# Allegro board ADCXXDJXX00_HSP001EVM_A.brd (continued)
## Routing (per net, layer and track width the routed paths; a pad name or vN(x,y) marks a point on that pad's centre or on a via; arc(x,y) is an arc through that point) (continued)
V3P3V:
  vias: v1(97.41,9.27) v1(97.41,7.24) v1(97.79,15.37) v1(98.3,7.75) v1(99.19,8.38) v1(99.44,15.75) v1(99.44,12.95) v1(99.49,11.33) v1(99.49,10.21) v1(100.69,13.03) v1(100.71,9.02) v1(100.97,10.54) v1(102.11,14.22) v1(102.11,11.94) v1(103.73,13) v1(104.27,11.81)
V3P3V_LMX: length 0.7
  BOTTOM w0.305: U22.20 81.5,7.71 v1(81.53,7.75)
  vias: v1(80.39,15.75) v1(80.39,14.86) v1(80.52,9.4) v1(80.52,7.37) v1(81.41,15.75) v1(81.41,14.99) v1(81.92,9.14) v1(82.17,8.38) v1(82.42,13.97) v1(82.42,12.32) v1(82.6,11.33) v1(82.6,10.21) v1(82.8,14.86) v1(83.31,15.87) v1(83.69,13.59) v1(83.82,12.45) v1(83.82,10.29) v1(83.82,9.02) v1(83.95,11.43) v1(84.96,12.32) v1(84.96,10.92) v1(85.47,9.52) v1(86.11,11.94) v1(86.11,10.79) v1(86.87,12.32) v1(87.25,10.79) v1(87.5,9.52)
V11_OUT:
  vias: v1(67.82,5.46) v1(69.09,7.37) v1(69.16,6.4) v1(69.34,5.33) v1(69.98,6.1) v1(70.48,5.33) v1(70.61,6.96) v1(71.79,6.25) v1(71.88,7.49) v1(72.01,5.23) v1(72.39,6.86) v1(72.77,6.1) v1(73.53,6.98) v1(73.53,5.23)
V19_SNS: length 12.2
  BOTTOM w0.254: FB16.1 42.29,19.18 42.55,18.92 45.47,18.92 45.47,18.93
  BOTTOM w0.305: U16.2 47.22,20.72 R149.1 46.57,20.28 U16.1 46.37,19.3 45.85,19.3 45.47,18.93 U16.20 U16.19
VBUS:
  vias: v1(32.95,14)
VBUSS: length 1.9
  BOTTOM w0.305: C173.1 31.34,16.29 31.05,16.58 v1(31.05,17.5)
VCCIN: length 2.3
  TOP w0.381: C104.2 65.88,114.68 v1(66.02,114.53)
  BOTTOM w0.305: v1(66.02,114.53) 65.92,114.64 U3.10
VDDD33: length 26.2
  TOP w0.127: U2.2 v1(25.96,111.2)
  TOP w0.254: U11.8 v1(76.2,35.48) ; U11.7 v1(76.22,36.13) ; U11.2 77.61,39.66 v1(77.62,39.66) 77.62,40.03 U11.1 U11.16
  TOP w0.305: U8.56 v1(59.31,44.61) ; v1(87.62,50.67) 87.62,49.79 U12.16 ; U8.20 v1(56.8,33.62) ; v1(62.31,33.48) U8.31 ; U8.42 v1(64.76,39.87)
  TOP w0.356: U10.2 48.66,29.33 v1(48.67,29.34) 48.67,29.57 U10.1 ; U10.8 v1(49.77,25.03) ; U10.16 v1(54.31,30.05)
  TOP w0.508: v1(74.36,46.5) v1(74.36,45.36)
  BOTTOM w0.127: C41.1 25.97,111.22 v1(25.96,111.2)
  BOTTOM w0.305: C187.1 63.31,39.87 v1(64.76,39.87) ; C189.1 59.31,44.61 v1(59.31,44.61) ; C188.1 v1(62.31,33.48) ; v1(56.8,33.62) C186.1
  BOTTOM w0.508: v1(77.02,50.71) 76.95,50.64 C180.1 ; FB12.1 51.82,43.81 v1(52.2,44.2)
  vias: v1(26.47,112.36) v1(29.26,113.25) v1(32.94,112.49) v1(32.94,111.34) v1(32.94,110.2) v1(32.94,109.06) v1(42.14,102.28) v1(42.13,99.86) v1(42.65,102.79) v1(42.65,101.77) v1(42.76,99.09) v1(43.53,99.86) v1(43.53,98.33) v1(50.55,48.13) v1(51.03,36.36) v1(51.31,47.37) v1(51.38,37.59) v1(66.88,31.3) v1(68.96,41.27) v1(68.96,38.99) v1(78.82,43.12) v1(92.08,13.34) v1(93.34,19.3) v1(93.34,16.13) v1(93.34,14.6) v1(93.34,12.06) v1(94.61,13.34) v1(96.01,16) v1(96.52,18.92) v1(96.77,18.16) v1(96.77,16.76) v1(97.16,21.59) v1(97.16,20.83) v1(97.28,19.43) v1(97.41,17.4) v1(97.82,20.19) v1(97.79,18.41) v1(98.42,19.43) v1(98.55,21.59) v1(98.55,20.83) v1(107.98,43.69) v1(110.24,39.75)
VDDL19: length 6.5
  TOP w0.305: v1(85.86,49.14) 87.57,49.14 U12.15 ; U11.15 v1(81.75,39.38)
  BOTTOM w0.508: v1(81.75,39.38) 81.78,39.41 C193.1 ; C195.1 v1(85.86,49.14)
  vias: v1(45.21,22.35) v1(45.21,20.7) v1(45.82,21.46) v1(45.97,23.24) v1(46.35,22.35) v1(46.74,22.99) v1(47.35,22.23) v1(47.62,22.99) v1(51.18,28.19) v1(51.18,27.3) v1(51.18,26.42) v1(51.69,26.92) v1(51.69,26.16) v1(51.82,28.7) v1(51.82,27.81) v1(52.32,25.78) v1(52.45,27.05) v1(52.58,28.83) v1(52.58,27.81) v1(52.83,26.29) v1(53.21,28.96) v1(54.31,28.93) v1(72.97,47.82) v1(73.05,47.04) v1(73.66,48.17) v1(73.77,47.38)
VINA: length 14.5
  TOP w0.279: J2.1 BALUN1.1
VINB: length 14.5
  TOP w0.279: J5.1 BALUN2.1
1P4V: length 2.3
  TOP w0.279: U17.6 v1(52.58,6.6) ; v1(52.58,9.91) v1(52.58,11.3)
  vias: v1(51.49,12.73) v1(51.49,11.33) v1(51.49,9.94) v1(52.58,12.7)
1P8V_USB: length 52.8
  TOP w0.305: v1(64.67,37.36) U8.37 ; U8.49 62.81,45.28 v1(63.12,45.59) ; U8.64 v1(55.3,44.51) ; v1(53.8,37.36) U8.12
  L10_SIG-2 w0.508: v1(44.07,33.4) 53.98,33.4 54.86,34.29 54.86,37.46
  BOTTOM w0.254: v1(55.3,44.51) 55.3,43.57 C181.1
  BOTTOM w0.279: v1(53.8,37.36) 54.05,37.11 C182.1 54.61,36.98 54.61,34.67 ; 65.03,37 v1(64.67,37.36) C183.1
  BOTTOM w0.305: v1(63.12,45.59) 62.81,45.28 C179.1
  BOTTOM w0.508: 65.03,37 65.41,36.62 65.41,34.6 63.32,32.51 56.77,32.51 54.61,34.67 53.34,33.4 v1(44.07,33.4)
  vias: v1(62.74,46.1) v1(63.5,45.09)
2P2V: length 0.9
  TOP w0.279: U14.6 v1(38.27,7.16)
  vias: v1(37.02,13.48) v1(37.02,12.08) v1(37.02,10.68) v1(38.27,13.34) v1(38.27,11.94) v1(38.27,10.54)
3P3USB: length 16.9
  TOP w0.305: v1(52.65,37.59) 52.65,38.02 53.51,38.88 53.94,38.88 53.95,38.87 U8.9
  BOTTOM w0.254: v1(44.07,37.21) 46.07,37.21 47.11,38.25 50.47,38.25 51.71,39.5 53.72,39.5 54.36,38.86 53.95,38.86 53.91,38.9 53.31,38.9 C171.1
  BOTTOM w0.279: v1(52.65,37.59) 53.15,38.09 53.15,38.75 C171.1
  BOTTOM w0.508: C170.1 54.36,38.86
3P3V_RX: length 19.5
  BOTTOM w0.279: v1(121.28,32.64) 123.95,32.64 125.98,34.67 137.58,34.67 139.06,36.15 v1(139.06,36.45)
3P3VAUX: length 29.7
  TOP w0.279: v1(122.73,36.45) 121.78,36.45 121.61,36.61 U5.8
  L10_SIG-2 w0.165: v1(122.73,36.45) 123.83,37.54 123.83,39.37 123.19,40 123.19,46.99
  BOTTOM w0.102: J25.D32 138.43,48.39 128.52,48.39
  BOTTOM w0.279: 123.19,46.99 124.59,48.39 128.52,48.39
12P0V_RX:
  vias: v1(140.33,45.21) v1(140.33,42.67)
ADBUS0: length 14.1
  TOP w0.279: U8.16 53.82,35.36 53.66,35.2 52.73,35.2 48.06,30.53 46.91,30.53 46.33,29.95 46.33,28.73 46.78,28.28 U10.3
ADBUS1: length 11.1
  TOP w0.279: U8.17 55.3,33.53 53.98,32.21 52.3,32.21 49.72,29.63 49.72,27.91 49.44,27.63 U10.4
ADBUS2: length 12.2
  TOP w0.279: U8.18 55.8,33.01 54.46,31.67 52.5,31.67 50.14,29.31 50.14,27.54 49.59,26.98 U10.5
ADBUS3: length 13.3
  TOP w0.279: U8.19 56.3,32.75 54.74,31.19 52.65,31.19 50.6,29.13 50.6,27.1 49.82,26.33 U10.6
ADC_CLK: length 86.9
  L04_SIG-1 w0.14: v1(43.88,45.25) 43.88,38.11 45.99,36 49.18,36 50.31,34.87 53.31,34.87 58.42,29.76 v1(58.42,29.59)
  L10_SIG-2 w0.102: v1(36.12,73.68) 35.72,74.08 33.52,74.08 33.33,74.27 33.33,77.36 33.33,77.36
  L10_SIG-2 w0.165: v1(43.88,45.25) 47.62,48.99 47.62,78.29 44.68,81.23 43.27,81.23 41.49,83 35.12,83 33.47,81.36 33.47,77.66 33.33,77.51 33.33,77.36
ADC_SCSB: length 72.3
  L04_SIG-1 w0.102: 32.62,69.16 32.52,69.26 32.52,73.07 32.74,73.28 35.51,73.28 35.73,73.5 35.73,74.08 v1(36.12,74.48)
  L04_SIG-1 w0.14: v1(58.42,26.16) 57.09,27.49 57.09,28.43 54.86,30.66 39.84,30.66 35.21,35.29 35.21,47.25 36.07,48.11 36.07,51.49 31.93,55.64 31.93,61.05 32.7,61.82 32.7,69.09 32.62,69.16
ADC_SDI: length 61.6
  L04_SIG-1 w0.089: 34.04,69.22 34.12,69.29
  L04_SIG-1 w0.102: 34.12,69.29 34.12,71.49 34.31,71.68 36.3,71.68 36.52,71.9 36.52,72.48 v1(36.12,72.88)
  L04_SIG-1 w0.14: v1(58.42,28.45) 53.6,33.27 45.55,33.27 39.9,38.92 39.9,47.08 38.14,48.84 38.14,52.74 35.64,55.25 35.64,61.14 33.99,62.78 33.99,69.16 34.04,69.22
ADC_SDO: length 67
  L04_SIG-1 w0.102: v1(36.12,72.08) 35.74,72.47 33.51,72.47 33.33,72.29 33.33,69.22
  L04_SIG-1 w0.14: 33.33,69.22 33.33,56.17 36.98,52.52 36.98,47.67 35.96,46.65 35.96,37.05 41.9,31.11 54.91,31.11 54.91,31.11 55.11,31.11 57.61,28.62 57.61,28.12 v1(58.42,27.3)
BDBUS0: length 2.9
  TOP w0.279: U8.26 59.81,31.63 R112.1
BDBUS1: length 6.4
  TOP w0.279: v1(60.31,33.55) U8.27 ; 64.18,30.35 v1(63.13,30.35)
  L10_SIG-2 w0.165: v1(60.31,33.55) 60.31,33.17 v1(63.13,30.35)
BDBUS2: length 3
  TOP w0.279: R113.1 60.81,31.78 U8.28
BDBUS3: length 5.2
  TOP w0.279: U7.1 62.93,31.3 61.31,32.93 U8.29
BYPASS: length 11.1
  BOTTOM w0.508: R159.1 FB18.1 71.81,14.25 72.57,13.49 74.78,13.49 FB19.1 74.8,11.46 73.53,10.19 73.53,9.02
CALTRG: length 30.3
  L04_SIG-1 w0.102: 34.92,78.04 34.92,77.4 35.05,77.28 35.48,77.28 35.71,77.05 35.71,76.67 35.92,76.47 36.4,76.47 36.52,76.34 36.52,75.05 36.37,74.89 35.99,74.89 35.57,74.48 v1(35.33,74.48)
  L04_SIG-1 w0.14: J9.2 36.06,96.22 34.57,94.74 34.57,86.89 33.82,86.14 33.82,80.41 34.92,79.31 34.92,78.04
  BOTTOM w0.279: R23.1 36.06,98.58 J9.2
CDBUS0: length 4.8
  TOP w0.279: U8.38 66.78,37.87 R118.1
CDBUS1: length 4.5
  TOP w0.279: U8.39 67.43,38.37 R119.1
CDBUS2: length 6.9
  TOP w0.279: U8.40 67.82,38.87 R115.2 68.58,39.62 69.34,39.62 R120.1
CDBUS3: length 7.7
  TOP w0.254: R114.2 67.94,40.51 68.33,40.13 R121.1
  TOP w0.279: U8.41 66.8,39.37 67.94,40.51
CE: length 5.3
  BOTTOM w0.279: U3.1 66.97,119.14 R46.1 67.79,119.96 68.81,119.96 JP5.2
CLK+: length 3.3
  TOP w0.279: C49.1 21.72,73.79 R43.2 20.12,74.37 arc(19.92,74.5) 19.69,74.55 T2.1
CLK-: length 3.3
  TOP w0.279: 18.86,72.01 19.69,72.01 arc(19.92,72.06) 20.12,72.19 R43.1 21.72,72.77 C52.1
CLK-IN: length 5.7
  BOTTOM w0.279: R69.1 T1.6 R67.1 R72.1 R70.2
CLK_+: length 8
  TOP w0.279: U1.F1 30.47,73.73 23.22,73.73 ; 23.22,73.73 23.04,73.73 C49.2 ; 23.22,73.73 23.22,73.73 v2(23.22,73.66)
  BOTTOM w0.279: C48.2 v2(23.22,73.66)
CLK_-: length 8
  TOP w0.279: U1.G1 30.47,72.83 23.22,72.83 ; v2(23.22,72.9) 23.22,72.83 ; 23.22,72.83 23.04,72.83 C52.2
  BOTTOM w0.279: C51.2 v2(23.22,72.9)
CLKIN0: length 27.9
  BOTTOM w0.279: R186.1 87.81,101.54 R187.1 86.26,101.54 arc(86.1,101.58) 85.96,101.67 85.73,101.89 arc(85.14,102.29) 84.43,102.43 J38.1
CLKIN0_N: length 3.7
  BOTTOM w0.254: U4.38 91.84,101.31 arc(91.09,101.46) 90.45,101.89 arc(90.26,102.01) 90.05,102.05 C24.2
CLKIN0_P: length 3.6
  BOTTOM w0.254: C20.2 90.28,101.29 arc(90.38,101.27) 90.46,101.22 90.58,101.09 arc(90.89,100.89) 91.24,100.82 93.43,100.82 U4.37
CLKIN1: length 0.7
  BOTTOM w0.279: R186.2 C20.1
CLKIN1_N: length 3.8
  BOTTOM w0.254: C136.2 90.52,99.94 C137.2 arc(90.77,99.88) 90.97,99.75 91.04,99.68 arc(91.18,99.58) 91.35,99.55 92.23,99.55 arc(92.38,99.58) 92.51,99.66 arc(92.66,99.77) 92.85,99.81 U4.35
CLKIN1_P: length 3.9
  BOTTOM w0.254: C134.2 90.35,99.18 arc(90.52,99.15) 90.66,99.05 arc(90.9,98.89) 91.18,98.84 92.14,98.84 arc(92.48,98.9) 92.76,99.09 92.84,99.17 arc(92.99,99.27) 93.17,99.31 U4.34
CLKINN: length 4.4
  BOTTOM w0.279: C136.1 87.43,99.94 R73.2 86.8,100.57 arc(86.57,100.73) 86.29,100.78 T1.3
CLKINP: length 5.1
  BOTTOM w0.279: C134.1 R68.1 87.53,99.18 R73.1 86.84,98.5 arc(86.56,98.31) 86.23,98.24 T1.1 R69.2
CLKLA_0N: length 5
  BOTTOM w0.152: R127.1 101.35,111.91 R90.1 101.16,111.06 101.16,107.74 101.27,107.63 U4.63
CLKLA_0P: length 5
  BOTTOM w0.152: U4.62 100.77,107.66 100.88,107.77 100.88,111.06 R89.1 100.69,111.91 R126.1
CLKM: length 105.4
  L10_SIG-2 w0.16: v4(19.47,76.93) 19.52,76.98 19.52,83.5 arc(19.88,85.34) 20.93,86.91 23.28,89.26 arc(24.47,90.05) 25.87,90.33 33.31,90.33 arc(33.9,90.21) 34.41,89.87 34.54,89.75 arc(34.92,89.49) 35.37,89.4 36.03,89.4 arc(36.33,89.46) 36.59,89.63 36.65,89.69 arc(37.13,90.01) 37.71,90.13 38.18,90.13 v4(38.23,90.17)
  BOTTOM w0.254: v4(19.47,76.93) 19.5,76.91 19.5,75 arc(20.1,73.53) 21.57,72.92 22.01,72.92 C53.1 ; C135.2 104.3,93.93 104.3,92.39 arc(103.64,90.8) 102.05,90.15 99.31,90.15 arc(99.21,90.17) 99.13,90.22 99,90.35 98.68,90.65 arc(98.6,90.69) 98.51,90.71 98.11,90.71 arc(97.99,90.69) 97.89,90.62 97.53,90.26 arc(97.4,90.18) 97.26,90.15 97.01,90.15 arc(96.87,90.17) 96.75,90.26 96.58,90.43 arc(96.28,90.62) 95.94,90.69 95.94,90.69 arc(95.58,90.62) 95.28,90.42 95.14,90.28 arc(95,90.19) 94.83,90.16 94.39,90.16 arc(94.21,90.19) 94.07,90.29 93.84,90.51 arc(93.64,90.65) 93.39,90.7 arc(93.12,90.65) 92.89,90.49 92.66,90.26 arc(92.53,90.17) 92.39,90.15 38.25,90.15 v4(38.23,90.17)
CLKP: length 105.4
  L10_SIG-2 w0.16: 37.71,89.46 37.71,89.46 ; 37.71,89.46 38.18,89.46 v4(38.23,89.41) ; 37.71,89.46 37.71,89.46 ; 37.71,89.46 arc(37.39,89.39) 37.12,89.21 37.07,89.16 arc(36.59,88.84) 36.03,88.73 35.37,88.73 arc(34.66,88.87) 34.06,89.27 33.94,89.4 arc(33.65,89.59) 33.31,89.66 32.14,89.66 arc(31.99,89.63) 31.86,89.54 31.68,89.36 arc(31.58,89.3) 31.47,89.28 31.19,89.28 arc(31.1,89.29) 31.02,89.35 30.82,89.54 arc(30.7,89.63) 30.55,89.66 25.87,89.66 arc(24.72,89.43) 23.75,88.78 21.4,86.43 arc(20.5,85.09) 20.19,83.5 20.19,83.18 arc(20.24,82.94) 20.37,82.74 20.47,82.64 arc(20.57,82.49) 20.6,82.31 arc(20.57,82.15) 20.48,82.02 20.46,81.99 20.37,81.91 20.3,81.83 arc(20.22,81.71) 20.19,81.57 20.19,81.46 arc(20.23,81.27) 20.33,81.11 20.47,80.97 arc(20.56,80.83) 20.6,80.67 20.6,80.67 arc(20.56,80.48) 20.46,80.33 20.37,80.24 20.28,80.16 arc(20.21,80.05) 20.19,79.92 20.19,79.74 arc(20.21,79.61) 20.29,79.49 20.37,79.41 20.54,79.24 arc(20.6,79.15) 20.62,79.05 arc(20.58,78.85) 20.47,78.68 20.37,78.58 arc(20.23,78.38) 20.19,78.14 20.19,76.98 v4(20.23,76.93)
  BOTTOM w0.254: v4(38.23,89.41) 38.25,89.44 102.05,89.44 arc(104.14,90.3) 105.01,92.39 105.01,93.93 C133.2 ; v4(20.23,76.93) 20.21,76.91 20.21,76.42 arc(20.25,76.32) 20.35,76.28 20.67,76.28 arc(20.86,76.2) 20.94,76.01 20.94,75.91 arc(20.86,75.72) 20.67,75.64 20.35,75.64 arc(20.25,75.59) 20.21,75.5 20.21,75 arc(20.61,74.03) 21.57,73.63 22.01,73.63 C48.1
CP1: length 38.5
  L04_SIG-1 w0.14: v1(94.21,95.96) 89.41,95.96 85.55,99.82 85.55,106.4 77.07,114.88 v1(77.07,118.82)
  BOTTOM w0.279: U4.32 94.27,96.01 v1(94.21,95.96) ; v1(77.07,118.82) 77.07,122.42 C130.1
CP2: length 4.8
  BOTTOM w0.127: C131.1 90.11,106.5
  BOTTOM w0.279: 90.11,106.5 91.19,106.5 92.38,105.31 U4.46 ; C132.1 C131.1
CPOUT: length 15.6
  TOP w0.279: v1(64.33,112.42) 64.41,112.34 66.4,112.34 66.91,112.85 66.91,121.18 v1(67.69,121.96)
  BOTTOM w0.254: v1(67.69,121.96) C119.1 C120.1
  BOTTOM w0.279: U3.12 63.8,112.95 v1(64.33,112.42)
DA0+: length 1.7
  TOP w0.254: C5.1 40.94,74.43 39.37,74.43 U1.E12
DA0-: length 1.7
  TOP w0.254: C6.1 40.95,73.72 39.37,73.72 U1.F12
DA0_M: length 102.2
  TOP w0.254: C6.2 41.63,73.75 124.08,73.75 v2(124.12,73.72)
  BOTTOM w0.254: J25.A11 142.58,75.4 arc(142.2,75.15) 141.76,75.06 128.55,75.06 arc(128.46,75.08) 128.37,75.13 128.24,75.26 arc(128.16,75.32) 128.06,75.34 127.66,75.34 arc(127.38,75.28) 127.13,75.12 126.37,74.35 arc(125.7,73.91) 124.91,73.75 124.14,73.75 v2(124.12,73.72)
DA0_P: length 102.2
  TOP w0.254: v2(124.12,74.49) 124.03,74.46 C5.2
  BOTTOM w0.254: J25.A10 142.52,76.61 arc(142.21,76.4) 141.84,76.33 128.55,76.33 arc(128.46,76.31) 128.37,76.25 128.24,76.12 arc(128.16,76.07) 128.06,76.05 127.66,76.05 arc(127.1,75.94) 126.63,75.62 125.87,74.86 arc(125.43,74.56) 124.91,74.46 124.14,74.46 v2(124.12,74.49)
DA1+: length 1.7
  TOP w0.254: C7.1 40.94,76.03 39.37,76.03 U1.C12
DA1-: length 1.7
  TOP w0.254: U1.D12 39.37,75.32 40.94,75.32 C8.1
DA1_M: length 102
  TOP w0.254: v2(118.56,78.46) 118.53,78.46 118.11,78.04 arc(117.61,77.71) 117.03,77.6 48.94,77.6 arc(47.55,77.32) 46.37,76.53 46.23,76.39 arc(45.04,75.6) 43.65,75.32 42.55,75.32 41.61,75.32 C8.2
  BOTTOM w0.254: J25.C7 140.33,80.59 arc(140.2,80.27) 139.88,80.14 138.99,80.14 129.02,80.13 128.67,80.13 arc(128.36,80.2) 128.09,80.37 127.69,80.78 arc(127.38,80.98) 127.02,81.05 124.97,81.05 arc(124.81,81.02) 124.67,80.93 124.18,80.44 arc(124.04,80.35) 123.88,80.32 123.76,80.32 arc(123.6,80.35) 123.46,80.44 122.98,80.92 arc(122.83,81.02) 122.65,81.05 122.08,81.05 arc(121.19,80.88) 120.43,80.37 118.56,78.5 v2(118.56,78.46)
DA1_P: length 102
  TOP w0.254: C7.2 41.6,76.03 42.85,76.03 43.65,76.03 arc(44.77,76.26) 45.72,76.89 45.86,77.03 arc(47.27,77.98) 48.94,78.31 112.8,78.31 arc(113.02,78.35) 113.2,78.47 113.62,78.89 arc(113.84,79.04) 114.1,79.09 114.29,79.09 arc(114.56,79.04) 114.78,78.89 115.09,78.58 115.22,78.46 arc(115.38,78.35) 115.57,78.31 117.03,78.31 arc(117.34,78.37) 117.6,78.55 118.02,78.97 v2(118.02,79)
  BOTTOM w0.254: v2(118.02,79) 118.06,79 119.93,80.87 arc(120.92,81.53) 122.08,81.77 127.02,81.77 arc(127.38,81.84) 127.69,82.04 128.08,82.44 arc(128.35,82.62) 128.67,82.68 129.02,82.68 138.99,82.68 139.88,82.68 arc(140.2,82.54) 140.33,82.22 J25.C6
DA2+: length 1.7
  TOP w0.254: U1.A10 37.77,77.72 37.77,79.3 C9.1
DA2-: length 1.7
  TOP w0.254: U1.A11 38.48,77.72 38.48,79.3 C10.1
DA2_M: length 111.5
  TOP w0.254: C10.2 38.48,79.96 38.48,80.74 arc(39.14,82.33) 40.73,82.99 42.22,82.99 arc(42.41,82.95) 42.57,82.84 42.7,82.71 42.84,82.58 arc(43.02,82.46) 43.23,82.41 43.4,82.41 arc(43.64,82.46) 43.85,82.6 43.96,82.71 44.09,82.84 arc(44.25,82.95) 44.45,82.99 45.17,82.99 arc(45.37,82.95) 45.53,82.84 45.66,82.71 45.8,82.58 arc(45.95,82.47) 46.13,82.44 46.42,82.44 arc(46.63,82.48) 46.81,82.6 46.92,82.71 47.05,82.84 arc(47.21,82.95) 47.41,82.99 48.24,82.99 arc(48.43,82.95) 48.6,82.84 48.72,82.71 48.86,82.58 arc(49.04,82.46) 49.26,82.41 49.42,82.41 arc(49.66,82.46) 49.87,82.6 49.99,82.71 50.11,82.84 arc(50.28,82.95) 50.47,82.99 108.75,82.99 arc(109.98,83.23) 111.02,83.93 arc(111.5,84.25) 112.06,84.36 136.2,84.36 arc(136.67,84.16) 136.86,83.7 136.86,81.8 arc(137.27,80.82) 138.26,80.41 140.97,80.41 arc(141.1,80.38) 141.21,80.31 arc(141.36,80.21) 141.53,80.18 142.28,80.18 arc(142.7,80.35) v2(142.88,80.77)
DA2_P: length 111.5
  TOP w0.254: C9.2 37.77,79.96 37.77,80.74 arc(38.64,82.83) 40.73,83.7 108.75,83.7 arc(109.71,83.89) 110.52,84.43 arc(111.22,84.9) 112.05,85.07 136.2,85.07 arc(137.17,84.67) 137.57,83.7 137.57,81.8 arc(137.77,81.32) 138.26,81.12 140.72,81.12 arc(140.95,81.17) 141.15,81.3 141.16,81.31 arc(141.29,81.4) 141.45,81.43 142.26,81.43 arc(142.69,81.61) v2(142.88,82.04)
DA3+: length 1.7
  TOP w0.254: C11.1 36.17,79.3 36.17,77.72 U1.A8
DA3-: length 1.7
  TOP w0.254: C12.1 36.88,79.3 36.88,77.72 U1.A9
DA3_M: length 111.8
  TOP w0.254: v2(106.68,85.86) 106.65,85.88 49.4,85.88 arc(49.21,85.84) 49.04,85.73 48.92,85.61 48.8,85.49 arc(48.62,85.37) 48.41,85.33 48.13,85.33 arc(47.94,85.37) 47.79,85.47 47.65,85.61 47.53,85.73 arc(47.36,85.84) 47.17,85.88 46.7,85.88 arc(46.5,85.84) 46.34,85.73 46.21,85.61 46.1,85.49 arc(45.92,85.37) 45.71,85.33 45.42,85.33 arc(45.24,85.37) 45.09,85.47 44.95,85.61 44.82,85.73 arc(44.66,85.84) 44.47,85.88 43.93,85.88 arc(43.74,85.84) 43.57,85.73 43.44,85.61 43.33,85.49 arc(43.15,85.37) 42.94,85.33 42.65,85.33 arc(42.47,85.37) 42.32,85.47 42.18,85.61 42.05,85.73 arc(41.89,85.84) 41.7,85.88 41.09,85.88 arc(38.11,84.65) 36.88,81.67 36.88,79.96 C12.2
  BOTTOM w0.254: J25.A3 142.58,86.14 arc(142.2,86.4) 141.76,86.49 128.55,86.49 arc(128.46,86.51) 128.37,86.56 128.24,86.69 arc(128.16,86.75) 128.06,86.77 115.93,86.77 arc(115.43,86.67) 115.01,86.38 arc(114.45,86.01) 113.79,85.88 106.7,85.88 v2(106.68,85.86)
DA3_P: length 111.8
  TOP w0.254: v2(106.68,86.62) 106.65,86.59 41.09,86.59 arc(37.61,85.15) 36.17,81.67 36.17,79.96 C11.2
  BOTTOM w0.254: v2(106.68,86.62) 106.7,86.59 113.79,86.59 arc(114.18,86.67) 114.5,86.89 arc(115.16,87.32) 115.93,87.48 128.06,87.48 arc(128.16,87.5) 128.24,87.55 128.37,87.68 arc(128.46,87.74) 128.55,87.76 141.76,87.76 arc(142.2,87.67) 142.58,87.41 J25.A2
DA4+: length 1.7
  BOTTOM w0.254: v1(38.52,74.48) 38.57,74.43 40.13,74.43 C13.1
DA4-: length 1.7
  BOTTOM w0.254: v1(38.52,73.68) 38.57,73.72 40.13,73.72 C15.1
DA4_M: length 107.9
  L10_SIG-2 w0.16: v4(107.38,71.85) 107.45,71.85 107.98,71.32 arc(108.65,70.87) 109.45,70.71 115.79,70.71 arc(117.03,70.47) 118.08,69.76 arc(119.58,68.76) 121.35,68.41 136.59,68.41 arc(137.89,68.67) 138.98,69.4 139.03,69.44 arc(139.93,70.04) 140.99,70.26 141.1,70.26 arc(141.2,70.24) 141.3,70.21 arc(141.36,70.17) 141.41,70.13 arc(141.59,70.01) 141.79,69.97 144.95,69.97 arc(145.28,70.11) 145.42,70.44 v4(145.42,70.61)
  BOTTOM w0.254: v4(107.38,71.85) 107.38,71.89 106.32,72.95 arc(105.47,73.52) 104.46,73.72 104.01,73.72 arc(103.82,73.68) 103.65,73.57 103.53,73.45 103.23,73.15 arc(103,73) 102.72,72.94 102.3,72.94 arc(102.03,73) 101.79,73.15 101.34,73.61 arc(101.21,73.69) 101.06,73.72 40.79,73.72 C15.2
DA4_P: length 107.9
  L10_SIG-2 w0.16: v4(107.92,72.39) 107.92,72.33 108.46,71.79 arc(108.91,71.49) 109.45,71.38 109.66,71.38 arc(109.8,71.41) 109.91,71.48 110.09,71.67 arc(110.2,71.74) 110.32,71.76 110.75,71.76 arc(110.86,71.74) 110.95,71.68 110.96,71.67 111.11,71.52 arc(111.26,71.42) 111.45,71.38 111.92,71.38 arc(112.05,71.41) 112.17,71.48 112.35,71.67 arc(112.47,71.75) 112.61,71.78 112.98,71.78 arc(113.1,71.75) 113.21,71.68 113.21,71.67 113.37,71.52 arc(113.52,71.42) 113.71,71.38 115.79,71.38 arc(117.29,71.09) 118.55,70.24 arc(119.84,69.38) 121.35,69.08 136.59,69.08 arc(137.63,69.28) 138.51,69.87 138.55,69.92 arc(139.67,70.66) 140.99,70.93 141.09,70.93 arc(141.21,70.95) 141.31,71.02 141.34,71.04 141.43,71.14 arc(141.55,71.22) 141.7,71.25 144.95,71.25 arc(145.28,71.38) 145.42,71.71 v4(145.42,71.88)
  BOTTOM w0.254: C13.2 40.79,74.43 104.46,74.43 arc(105.74,74.18) 106.82,73.46 107.88,72.39 v4(107.92,72.39)
DA5+: length 1.7
  BOTTOM w0.254: C16.1 40.13,76.03 38.57,76.03 v1(38.52,76.08)
DA5-: length 1.7
  BOTTOM w0.254: C18.1 40.13,75.32 38.57,75.32 v1(38.52,75.28)
DA5_M: length 108.1
  L10_SIG-2 w0.16: v4(121.92,77.13) 121.97,77.17 125.35,77.17 arc(126.37,76.97) 127.23,76.4 127.7,75.92 arc(128.37,75.48) 129.15,75.32 134.43,75.32 arc(134.66,75.27) 134.86,75.14 arc(134.99,75.05) 135.14,75.02 136.31,75.02 arc(137.15,75.19) 137.86,75.66 arc(138.59,76.15) 139.45,76.33 143.88,76.33 arc(144.71,76.16) v4(145.42,75.69)
  BOTTOM w0.254: C18.2 40.79,75.32 43.54,75.32 arc(44.62,75.54) 45.54,76.15 46.99,77.61 arc(47.91,78.22) 48.99,78.43 103.81,78.43 arc(105.23,78.15) 106.43,77.35 106.62,77.16 arc(108.21,76.09) 110.09,75.72 118.75,75.72 arc(119.54,75.88) 120.21,76.33 120.71,76.82 120.77,76.89 arc(121.06,77.08) 121.41,77.15 121.9,77.15 v4(121.92,77.13)
DA5_P: length 108.1
  L10_SIG-2 w0.16: v4(121.92,77.89) 121.97,77.84 125.35,77.84 arc(126.62,77.59) 127.7,76.87 128.18,76.4 arc(128.62,76.1) 129.15,75.99 134.44,75.99 arc(134.69,76.04) 134.89,76.18 arc(135.06,76.29) 135.25,76.33 136.4,76.33 arc(136.89,76.42) 137.31,76.7 arc(138.31,77.37) 139.5,77.61 143.85,77.61 arc(144.7,77.44) v4(145.42,76.96)
  BOTTOM w0.254: C16.2 40.79,76.03 43.54,76.03 arc(44.35,76.2) 45.03,76.66 46.49,78.11 arc(47.63,78.87) 48.99,79.14 103.81,79.14 arc(105.5,78.81) 106.93,77.85 107.12,77.66 arc(108.48,76.75) 110.09,76.43 118.75,76.43 arc(119.27,76.54) 119.71,76.83 120.2,77.33 120.27,77.39 arc(120.79,77.74) 121.41,77.86 121.9,77.86 v4(121.92,77.89)
DA6+: length 1.7
  BOTTOM w0.254: C19.1 37.76,78.48 37.76,76.91 v1(37.73,76.88)
DA6-: length 1.7
  BOTTOM w0.254: v1(38.52,76.88) 38.47,76.94 38.47,78.48 C21.1
DA6_M: length 109
  L10_SIG-2 w0.16: v4(141.61,78.23) 141.49,78.34 arc(140.94,78.71) 140.28,78.84 135.51,78.84 arc(135.33,78.88) 135.18,78.98 arc(134.99,79.11) 134.77,79.15 133.87,79.15 arc(132.78,79.36) 131.87,79.98 130.22,81.62 arc(129.65,82) 128.98,82.14 116.19,82.14 arc(115.44,81.99) 114.81,81.56 114.57,81.32 arc(113.91,80.88) 113.13,80.73 110.92,80.73 v4(110.87,80.68)
  BOTTOM w0.254: v4(110.87,80.68) 110.85,80.71 108.47,80.71 arc(106.95,81.01) 105.65,81.87 arc(104.41,82.7) 102.95,82.99 50.34,82.99 arc(50.15,82.95) 49.98,82.84 49.85,82.72 49.74,82.6 arc(49.56,82.48) 49.35,82.44 49.06,82.44 arc(48.88,82.48) 48.73,82.58 48.59,82.72 48.46,82.84 arc(48.3,82.95) 48.11,82.99 47.45,82.99 arc(47.25,82.95) 47.09,82.84 46.96,82.72 46.85,82.6 arc(46.67,82.48) 46.46,82.44 46.17,82.44 arc(45.99,82.48) 45.84,82.58 45.7,82.72 45.57,82.84 arc(45.41,82.95) 45.22,82.99 44.57,82.99 arc(44.38,82.95) 44.21,82.84 44.09,82.72 43.97,82.6 arc(43.79,82.48) 43.58,82.44 43.3,82.44 arc(43.11,82.48) 42.96,82.58 42.82,82.72 42.69,82.84 arc(42.53,82.95) 42.34,82.99 41.89,82.99 arc(39.47,81.99) 38.47,79.57 38.47,79.14 C21.2
DA6_P: length 109
  L10_SIG-2 w0.16: v4(110.87,81.44) 110.92,81.4 113.13,81.4 arc(113.65,81.5) 114.09,81.8 114.34,82.04 arc(115.19,82.61) 116.19,82.81 128.98,82.81 arc(129.91,82.62) 130.7,82.09 132.34,80.45 arc(133.04,79.98) 133.87,79.82 134.75,79.82 arc(134.92,79.85) 135.05,79.94 arc(135.24,80.07) 135.47,80.11 140.28,80.11 arc(140.94,79.98) 141.49,79.61 v4(141.61,79.5)
  BOTTOM w0.254: v4(110.87,81.44) 110.85,81.42 108.47,81.42 arc(107.22,81.67) 106.15,82.38 arc(104.69,83.36) 102.95,83.7 41.89,83.7 arc(38.97,82.49) 37.76,79.57 37.76,79.14 C19.2
DA7+: length 1.6
  BOTTOM w0.254: v1(36.12,76.88) 36.16,76.91 C22.1
DA7-: length 1.6
  BOTTOM w0.254: v1(36.92,76.88) 36.92,76.89 C23.1
DA7_M: length 115.7
  L10_SIG-2 w0.16: v4(108.88,88.97) 108.93,89.02 109.8,89.02 arc(110.66,88.85) 111.39,88.36 113.28,86.47 arc(114.37,85.74) 115.66,85.48 135.83,85.48 arc(136.4,85.6) 136.88,85.92 137.05,86.08 arc(137.5,86.38) 138.03,86.49 139.43,86.49 arc(139.82,86.33) 139.98,85.94 139.98,84.79 arc(140.32,83.98) 141.13,83.64 141.27,83.64 arc(141.51,83.55) v4(141.61,83.31)
  BOTTOM w0.254: C23.2 36.89,79.14 36.89,81.33 arc(38.49,85.19) 42.36,86.79 43.68,86.79 arc(43.87,86.76) 44.04,86.65 44.16,86.52 44.16,86.52 44.3,86.38 arc(44.46,86.28) 44.64,86.24 44.91,86.24 arc(45.13,86.28) 45.31,86.41 45.43,86.52 45.43,86.52 45.55,86.65 arc(45.72,86.76) 45.91,86.79 46.69,86.79 arc(46.89,86.76) 47.05,86.65 47.18,86.52 47.18,86.52 47.32,86.38 arc(47.47,86.28) 47.65,86.24 47.93,86.24 arc(48.15,86.29) 48.33,86.41 48.44,86.52 48.44,86.52 48.57,86.65 arc(48.73,86.76) 48.93,86.79 49.77,86.79 arc(49.96,86.76) 50.12,86.65 50.25,86.52 50.25,86.52 50.39,86.38 arc(50.54,86.28) 50.72,86.24 51.01,86.24 arc(51.22,86.29) 51.4,86.41 51.51,86.52 51.51,86.52 51.64,86.65 arc(51.8,86.76) 52,86.79 101.5,86.79 101.5,86.79 103.23,86.79 arc(104.13,86.97) 104.89,87.48 105.82,88.42 arc(106.47,88.85) 107.22,89 108.86,89 v4(108.88,88.97)
DA7_P: length 115.8
  L10_SIG-2 w0.16: v4(141.61,84.58) 141.61,84.48 arc(141.55,84.36) 141.43,84.31 141.13,84.31 arc(140.79,84.45) 140.65,84.79 140.65,85.94 arc(140.29,86.8) 139.43,87.16 138.03,87.16 arc(137.24,87) 136.57,86.56 136.41,86.39 arc(136.14,86.22) 135.83,86.15 115.66,86.15 arc(114.63,86.36) 113.76,86.94 111.87,88.83 arc(110.92,89.47) 109.8,89.69 108.93,89.69 v4(108.88,89.73)
  BOTTOM w0.254: v4(108.88,89.73) 108.86,89.71 107.22,89.71 arc(106.19,89.5) 105.32,88.92 104.38,87.98 arc(103.86,87.63) 103.23,87.51 102.12,87.51 42.36,87.51 arc(37.99,85.7) 36.18,81.33 36.18,79.14 C22.2
DB0+: length 1.7
  TOP w0.254: U1.H12 39.37,72.12 40.95,72.12 C25.1
DB0-: length 1.7
  TOP w0.254: U1.G12 39.37,72.83 40.94,72.83 C26.1
DB0_M: length 103.2
  TOP w0.254: C26.2 41.61,72.83 43.83,72.83 arc(45.15,72.57) 46.27,71.83 46.93,71.16 arc(47.91,70.51) 49.06,70.28 116.92,70.28 arc(118.01,70.06) 118.94,69.44 arc(119.8,68.87) 120.82,68.67 131.38,68.67 arc(134.66,69.32) 137.44,71.18 139.99,73.73 arc(140.45,74.04) 140.99,74.14 141.33,74.14 arc(141.52,74.22) v2(141.61,74.42)
DB0_P: length 103.2
  TOP w0.254: C25.2 41.6,72.12 43.83,72.12 arc(44.88,71.92) 45.77,71.32 46.43,70.66 arc(47.64,69.85) 49.06,69.57 116.92,69.57 arc(117.74,69.41) 118.44,68.94 arc(119.53,68.21) 120.82,67.96 131.38,67.96 arc(134.93,68.66) 137.94,70.67 140.5,73.23 arc(140.72,73.38) 140.99,73.43 141.33,73.43 arc(141.52,73.35) v2(141.61,73.15)
DB1+: length 1.7
  TOP w0.254: U1.K12 39.37,70.52 40.94,70.52 C27.1
DB1-: length 1.7
  TOP w0.254: C28.1 40.94,71.23 39.37,71.23 U1.J12
DB1_M: length 105.6
  TOP w0.254: C28.2 41.61,71.23 42.16,71.23 arc(43.38,70.99) 44.42,70.3 47.02,67.7 arc(48.69,66.59) 50.66,66.2 116.95,66.2 v2(116.96,66.22)
  BOTTOM w0.254: v2(116.96,66.22) 116.98,66.2 118.87,66.2 arc(119.52,66.33) 120.07,66.7 124.27,70.89 arc(125.76,71.89) 127.52,72.24 128.06,72.24 arc(128.16,72.26) 128.24,72.31 128.37,72.44 arc(128.46,72.5) 128.55,72.52 141.76,72.52 arc(142.2,72.43) 142.58,72.17 J25.A14
DB1_P: length 105.6
  TOP w0.254: C27.2 41.61,70.52 42.16,70.52 arc(43.11,70.33) 43.92,69.8 46.51,67.2 arc(48.41,65.93) 50.65,65.49 116.9,65.49 v2(116.96,65.46)
  BOTTOM w0.254: v2(116.96,65.46) 116.98,65.49 118.87,65.49 arc(119.79,65.67) 120.58,66.19 124.77,70.39 arc(126.03,71.23) 127.52,71.53 128.06,71.53 arc(128.16,71.51) 128.24,71.45 128.37,71.32 arc(128.46,71.27) 128.55,71.25 141.84,71.25 arc(142.21,71.17) 142.52,70.97 J25.A15
DB2+: length 1.7
  TOP w0.254: C29.1 37.77,67.26 37.77,68.83 U1.M10
DB2-: length 1.7
  TOP w0.254: C30.1 38.48,67.26 38.48,68.83 U1.M11
DB2_M: length 109.1
  TOP w0.254: C30.2 38.48,66.6 38.48,65.65 arc(39.25,63.8) 41.1,63.03 42.48,63.03 arc(42.68,63.07) 42.84,63.18 42.97,63.31 43.08,63.42 arc(43.26,63.54) 43.48,63.58 43.76,63.58 arc(43.94,63.55) 44.1,63.44 44.23,63.31 44.36,63.18 arc(44.52,63.07) 44.72,63.03 45.22,63.03 arc(45.42,63.07) 45.58,63.18 45.71,63.31 45.82,63.42 arc(46,63.54) 46.21,63.58 46.5,63.58 arc(46.68,63.55) 46.83,63.44 46.97,63.31 47.1,63.18 arc(47.26,63.07) 47.45,63.03 48,63.03 arc(48.2,63.07) 48.36,63.18 48.49,63.31 48.6,63.42 arc(48.78,63.54) 48.99,63.58 49.28,63.58 arc(49.46,63.55) 49.61,63.44 49.75,63.31 49.88,63.18 arc(50.04,63.07) 50.23,63.03 119.15,63.03 v2(119.17,63.06)
  BOTTOM w0.254: v2(119.17,63.06) 119.2,63.03 119.93,63.03 arc(120.62,63.17) 121.21,63.56 125.62,67.97 arc(126.12,68.31) 126.72,68.43 127.81,68.43 arc(127.91,68.45) 127.99,68.5 128.12,68.63 arc(128.2,68.69) 128.3,68.71 140.57,68.71 arc(140.94,68.78) 141.25,68.99 J25.B16
DB2_P: length 109.1
  TOP w0.254: v2(119.17,62.3) 119.1,62.32 41.1,62.32 arc(38.74,63.3) 37.77,65.65 37.77,66.6 C29.2
  BOTTOM w0.254: v2(119.17,62.3) 119.2,62.32 119.93,62.32 arc(120.89,62.51) 121.71,63.06 126.12,67.47 arc(126.4,67.65) 126.72,67.72 127.81,67.72 arc(127.91,67.7) 127.99,67.64 128.12,67.51 arc(128.2,67.46) 128.3,67.44 140.49,67.44 arc(140.93,67.53) 141.31,67.78 J25.B17
DB3+: length 1.7
  TOP w0.254: U1.M8 36.17,68.83 36.17,67.26 C31.1
DB3-: length 1.7
  TOP w0.254: U1.M9 36.88,68.83 36.88,67.26 C32.1
DB3_M: length 115.7
  TOP w0.254: v2(115.71,58.89) 115.69,58.86 50.63,58.86 arc(50.44,58.9) 50.27,59.01 50.15,59.14 50.01,59.27 arc(49.85,59.38) 49.67,59.41 49.39,59.41 arc(49.18,59.37) 49,59.25 48.88,59.14 48.76,59.01 arc(48.59,58.9) 48.4,58.86 48.09,58.86 arc(47.9,58.9) 47.73,59.01 47.61,59.14 47.47,59.27 arc(47.32,59.38) 47.13,59.41 46.85,59.41 arc(46.64,59.37) 46.46,59.25 46.34,59.14 46.22,59.01 arc(46.05,58.9) 45.86,58.86 45.36,58.86 arc(45.17,58.9) 45,59.01 44.88,59.14 44.74,59.27 arc(44.58,59.38) 44.4,59.41 44.12,59.41 arc(43.91,59.37) 43.73,59.25 43.61,59.14 43.49,59.01 arc(43.32,58.9) 43.13,58.86 41.99,58.86 arc(38.38,60.36) 36.88,63.97 36.88,66.6 C32.2
  BOTTOM w0.254: J25.A18 142.52,66.45 arc(142.21,66.24) 141.84,66.17 128.55,66.17 arc(128.46,66.15) 128.37,66.09 128.24,65.96 arc(128.16,65.91) 128.06,65.89 127.45,65.89 arc(126.88,65.78) 126.41,65.46 121.26,60.31 arc(119.65,59.24) 117.76,58.86 115.74,58.86 v2(115.71,58.89)
DB3_P: length 115.7
  TOP w0.254: v2(115.71,58.13) 115.69,58.15 41.99,58.15 arc(37.87,59.85) 36.17,63.97 36.17,66.6 C31.2
  BOTTOM w0.254: v2(115.71,58.13) 115.74,58.15 117.76,58.15 arc(119.93,58.58) 121.76,59.81 126.91,64.95 arc(127.16,65.12) 127.45,65.18 128.06,65.18 arc(128.16,65.16) 128.24,65.1 128.37,64.97 arc(128.46,64.92) 128.55,64.9 141.76,64.9 arc(142.2,64.99) 142.58,65.24 J25.A19
DB4+: length 1.7
  BOTTOM w0.254: v1(38.52,72.08) 38.57,72.12 40.13,72.12 C33.1
DB4-: length 1.7
  BOTTOM w0.254: v1(38.52,72.88) 38.57,72.83 40.13,72.83 C34.1
DB4_M: length 106.6
  L10_SIG-2 w0.16: v4(144.14,74.42) 144.14,74.63 arc(144.02,74.92) 143.73,75.04 141.81,75.04 arc(141.31,74.94) 140.89,74.66 140.42,74.19 arc(140.34,74.13) 140.23,74.11 140.1,74.11 arc(138.75,73.84) 137.6,73.08 136.09,71.56 arc(135.77,71.35) 135.39,71.28 134.39,71.28 arc(133.99,71.36) 133.65,71.58 arc(133.1,71.95) 132.45,72.08 122.85,72.08 122.85,72.08 121.7,72.08 v4(121.65,72.13)
  BOTTOM w0.254: C34.2 40.79,72.83 43.24,72.83 arc(44.37,72.6) 45.33,71.96 arc(47.23,70.69) 49.47,70.25 109.95,70.25 arc(110.62,70.38) 111.18,70.76 111.58,71.15 arc(112.62,71.85) 113.86,72.1 121.63,72.1 v4(121.65,72.13)
DB4_P: length 106.6
  L10_SIG-2 w0.16: v4(121.65,71.36) 121.7,71.41 122.57,71.41 122.57,71.41 132.45,71.41 arc(132.84,71.33) 133.17,71.11 arc(133.73,70.74) 134.39,70.61 135.39,70.61 arc(136.02,70.73) 136.56,71.09 138.07,72.6 arc(139,73.23) 140.1,73.44 140.23,73.44 arc(140.34,73.42) 140.44,73.36 140.99,72.8 arc(141.29,72.6) 141.64,72.53 143.69,72.53 arc(144.01,72.67) 144.14,72.99 v4(144.14,73.15)
  BOTTOM w0.254: v4(121.65,71.36) 121.63,71.39 113.86,71.39 arc(112.9,71.2) 112.08,70.65 111.68,70.26 arc(110.89,69.72) 109.95,69.54 49.47,69.54 arc(46.96,70.04) 44.83,71.46 arc(44.1,71.95) 43.24,72.12 40.78,72.12 C33.2
DB5+: length 1.7
  BOTTOM w0.254: C35.1 40.13,70.52 38.57,70.52 v1(38.52,70.48)
DB5-: length 1.7
  BOTTOM w0.254: C36.1 40.13,71.23 38.57,71.23 v1(38.52,71.28)
DB5_M: length 108.1
  L10_SIG-2 w0.16: v4(144.14,69.34) 144.14,69.17 arc(144.01,68.84) 143.68,68.71 141.4,68.71 arc(141.15,68.66) 140.93,68.51 140.93,68.51 arc(140.8,68.42) 140.64,68.39 140.52,68.39 arc(139.29,68.15) 138.24,67.45 137.88,67.09 arc(137.25,66.66) 136.51,66.52 121.9,66.52 arc(120.05,66.89) 118.47,67.94 arc(117.15,68.82) 115.58,69.14 114.27,69.14 arc(113.65,69.01) 113.12,68.66 112.56,68.1 v4(112.49,68.1)
  BOTTOM w0.254: C36.2 40.79,71.23 41.33,71.23 arc(42.73,70.96) 43.91,70.17 44.4,69.68 45.42,68.66 45.72,68.36 arc(47.55,67.13) 49.72,66.7 106.48,66.7 arc(106.68,66.74) 106.85,66.86 107.28,67.29 arc(107.52,67.45) 107.79,67.5 108.12,67.5 arc(108.35,67.46) 108.54,67.33 108.89,66.98 109.01,66.85 arc(109.18,66.74) 109.37,66.7 110.42,66.7 arc(111.08,66.84) 111.64,67.21 112.49,68.06 v4(112.49,68.1)
DB5_P: length 108.1
  L10_SIG-2 w0.16: v4(144.14,68.07) 144.14,68 arc(143.98,67.6) 143.58,67.44 141.16,67.44 arc(141.09,67.45) 141.03,67.49 140.91,67.61 arc(140.79,67.69) 140.64,67.72 140.52,67.72 arc(139.55,67.53) 138.72,66.97 138.36,66.61 arc(137.51,66.05) 136.51,65.85 126.78,65.85 arc(126.65,65.82) 126.54,65.75 126.36,65.56 arc(126.21,65.46) 126.04,65.43 125.79,65.43 arc(125.63,65.46) 125.5,65.55 125.49,65.55 125.34,65.7 arc(125.19,65.81) 125,65.85 124.34,65.85 arc(124.2,65.82) 124.09,65.75 123.91,65.56 arc(123.75,65.45) 123.56,65.41 123.37,65.41 arc(123.2,65.45) 123.05,65.55 123.04,65.55 122.89,65.7 arc(122.74,65.81) 122.55,65.85 121.9,65.85 arc(119.79,66.27) 118,67.46 arc(116.89,68.2) 115.58,68.47 114.27,68.47 arc(113.9,68.39) 113.59,68.19 113.03,67.62 v4(113.03,67.56)
  BOTTOM w0.254: v4(113.03,67.56) 113,67.56 112.14,66.71 arc(111.35,66.18) 110.42,65.99 49.72,65.99 arc(47.28,66.48) 45.22,67.86 43.9,69.17 43.9,69.17 43.41,69.66 arc(42.46,70.3) 41.33,70.52 40.79,70.52 C35.2
DB6+: length 1.7
  BOTTOM w0.254: C37.1 37.77,68.08 37.77,69.63 v1(37.73,69.68)
DB6-: length 1.7
  BOTTOM w0.254: C38.1 38.48,68.08 38.48,69.63 v1(38.52,69.68)
DB6_M: length 117.3
  L10_SIG-2 w0.16: v4(110.83,60.88) 110.89,60.88 111.68,61.67 arc(112.47,62.2) 113.4,62.38 115.63,62.38 arc(116.37,62.23) 117,61.82 118.03,60.78 arc(118.7,60.33) 119.5,60.17 121.72,60.17 arc(121.73,60.17) 121.73,60.17 122.24,60.17 arc(122.34,60.18) 122.44,60.18 122.44,60.18 123.62,60.18 arc(124.07,60.27) 124.44,60.52 126.15,62.23 arc(127.36,63.04) 128.79,63.32 136.75,63.32 arc(137.51,63.47) 138.15,63.9 139.38,65.13 arc(140.18,65.66) 141.12,65.85 141.89,65.85 arc(142.04,65.88) 142.16,65.96 142.2,66.01 arc(142.38,66.13) 142.59,66.17 144.95,66.17 arc(145.28,66.3) 145.42,66.63 v4(145.42,66.8)
  BOTTOM w0.254: v4(110.83,60.88) 110.83,60.84 110.48,60.49 arc(109.62,59.92) 108.61,59.72 107.64,59.72 arc(107.45,59.75) 107.28,59.86 107.16,59.99 107.16,59.99 107.02,60.13 arc(106.8,60.27) 106.54,60.33 arc(106.25,60.27) 106.01,60.1 105.89,59.99 105.89,59.99 105.77,59.86 arc(105.6,59.75) 105.41,59.72 55.26,59.72 arc(55.06,59.75) 54.9,59.86 54.77,59.99 54.77,59.99 54.63,60.13 arc(54.36,60.31) 54.03,60.38 arc(53.67,60.31) 53.37,60.1 53.25,59.99 53.25,59.99 53.05,59.79 arc(52.97,59.73) 52.87,59.72 52.25,59.72 arc(52.05,59.75) 51.89,59.86 51.76,59.99 51.76,59.99 51.63,60.13 arc(51.41,60.27) 51.15,60.33 arc(50.86,60.27) 50.61,60.1 50.5,59.99 50.5,59.99 50.37,59.86 arc(50.21,59.75) 50.01,59.72 49.52,59.72 arc(49.33,59.75) 49.16,59.86 49.04,59.99 49.04,59.99 48.9,60.13 arc(48.64,60.3) 48.33,60.36 arc(47.99,60.3) 47.71,60.1 47.6,59.99 47.6,59.99 47.47,59.86 arc(47.3,59.75) 47.11,59.72 45.81,59.72 arc(40.63,61.86) 38.48,67.05 38.48,67.42 C38.2
DB6_P: length 117.3
  L10_SIG-2 w0.16: v4(111.37,60.34) 111.37,60.41 112.16,61.2 arc(112.73,61.58) 113.4,61.71 115.63,61.71 arc(116.11,61.62) 116.52,61.34 117.56,60.31 arc(118.45,59.71) 119.5,59.5 119.94,59.5 arc(120.12,59.47) 120.28,59.36 120.43,59.21 120.43,59.21 arc(120.61,59.1) 120.82,59.06 arc(121.11,59.11) 121.35,59.28 121.47,59.4 arc(121.59,59.48) 121.73,59.5 122.24,59.5 arc(122.36,59.51) 122.48,59.51 123.62,59.51 arc(124.32,59.65) 124.92,60.05 126.63,61.76 arc(127.62,62.42) 128.79,62.65 129.57,62.65 arc(129.75,62.62) 129.91,62.51 130.06,62.36 130.06,62.35 arc(130.25,62.23) 130.46,62.19 130.5,62.19 arc(130.73,62.24) 130.92,62.37 131.11,62.55 arc(131.22,62.63) 131.35,62.65 136.75,62.65 arc(137.77,62.85) 138.63,63.43 139.85,64.65 arc(140.44,65.04) 141.12,65.18 141.93,65.18 arc(142.11,65.14) 142.26,65.04 arc(142.42,64.93) 142.61,64.9 144.86,64.9 arc(145.25,65.06) 145.42,65.45 v4(145.42,65.53)
  BOTTOM w0.254: v4(111.37,60.34) 111.34,60.34 110.99,59.99 arc(109.89,59.26) 108.61,59 45.81,59 arc(40.12,61.36) 37.77,67.05 37.77,67.42 C37.2
DB7+: length 1.7
  BOTTOM w0.254: v1(36.12,69.68) 36.17,69.63 36.17,68.08 C39.1
DB7-: length 1.7
  BOTTOM w0.254: C40.1 36.88,68.08 36.88,69.63 v1(36.92,69.68)
DB7_M: length 121.3
  L10_SIG-2 w0.16: v4(145.42,61.72) 145.42,61.55 arc(145.28,61.22) 144.95,61.09 143.78,61.09 arc(143.61,61.05) 143.47,60.96 143.41,60.9 arc(143.27,60.8) 143.1,60.77 134.27,60.77 arc(131.93,60.3) 129.95,58.98 128.71,57.74 arc(126.49,56.26) 123.87,55.74 117.45,55.74 v4(117.41,55.78)
  BOTTOM w0.254: C40.2 36.88,67.42 36.88,60.75 arc(38.34,57.22) 41.87,55.75 42.46,55.75 arc(42.65,55.79) 42.81,55.9 42.94,56.03 42.94,56.03 43.05,56.14 arc(43.23,56.26) 43.45,56.3 43.73,56.3 arc(43.91,56.27) 44.07,56.17 44.2,56.03 44.2,56.03 44.33,55.9 arc(44.49,55.79) 44.69,55.75 45.08,55.75 arc(45.28,55.79) 45.44,55.9 45.57,56.03 45.57,56.03 45.68,56.14 arc(45.86,56.26) 46.08,56.3 46.36,56.3 arc(46.54,56.27) 46.7,56.17 46.83,56.03 46.83,56.03 46.96,55.9 arc(47.12,55.79) 47.32,55.75 47.6,55.75 arc(47.79,55.79) 47.96,55.9 48.09,56.03 48.09,56.03 48.2,56.14 arc(48.38,56.26) 48.59,56.3 48.88,56.3 arc(49.06,56.27) 49.21,56.17 49.35,56.03 49.35,56.03 49.48,55.9 arc(49.64,55.79) 49.83,55.75 115.88,55.75 115.88,55.76 117.38,55.76 v4(117.41,55.78)
DB7_P: length 121.3
  L10_SIG-2 w0.16: v4(145.42,60.45) 145.42,60.28 arc(145.28,59.95) 144.95,59.82 143.75,59.82 arc(143.59,59.85) 143.46,59.94 arc(143.28,60.06) 143.07,60.1 141.59,60.1 135.81,60.1 134.27,60.1 arc(132.19,59.68) 130.42,58.5 129.18,57.26 arc(126.74,55.64) 123.87,55.07 117.45,55.07 v4(117.41,55.02)
  BOTTOM w0.254: v4(117.41,55.02) 117.38,55.05 116.18,55.05 116.17,55.04 41.87,55.04 arc(37.84,56.71) 36.17,60.75 36.17,67.42 C39.2
DCLKOUT2_N: length 6.5
  BOTTOM w0.254: C135.1 104.27,95.22 R75.1 104.3,95.3 104.3,96.11 arc(104.21,96.31) 104.01,96.4 103.84,96.4 arc(103.63,96.49) 103.54,96.7 103.54,96.86 arc(103.62,97.04) 103.79,97.11 104.02,97.11 arc(104.22,97.19) 104.3,97.39 104.3,97.84 arc(104.26,98.02) 104.16,98.18 103.75,98.59 103.72,98.62 arc(103.57,98.73) 103.4,98.79 arc(103.34,98.8) 103.27,98.8 102.89,98.8 102.89,98.81 U4.16
DCLKOUT2_P: length 6.5
  BOTTOM w0.254: U4.15 103.68,99.31 arc(103.94,99.26) 104.16,99.11 104.29,98.97 104.54,98.72 104.81,98.45 arc(104.96,98.23) 105.01,97.98 105.01,95.3 R74.1 105.04,95.22 C133.1
DCLKOUT6_N: length 3.1
  BOTTOM w0.152: C153.1 R95.1 96.12,96.04 96.38,96.3 96.38,97.14 96.27,97.25 U4.28
DCLKOUT6_P: length 3.1
  BOTTOM w0.152: U4.27 96.77,97.25 96.66,97.14 96.66,96.26 96.88,96.04 R94.1 C151.1
DCLKOUT8_N: length 5.9
  BOTTOM w0.152: R24.1 93.54,111.16 R57.1 94.39,110.97 95.15,110.97 95.66,110.46 95.66,107.78 95.77,107.67 U4.52
DCLKOUT8_P: length 5.4
  BOTTOM w0.152: R22.1 93.54,110.5 R58.1 94.39,110.69 95.04,110.69 95.38,110.35 95.38,107.79 95.27,107.68 U4.51
DCLKOUT10_N: length 11.3
  TOP w0.254: v2(97.39,112.23) 97.36,112.25 97.36,112.73 arc(97.57,113.23) 98.07,113.44 100.55,113.44 arc(101.28,113.74) 101.58,114.47 J24.1
  BOTTOM w0.254: C143.2 97.36,110.13 97.36,112.2 v2(97.39,112.23)
DCLKOUT10_P: length 11.3
  TOP w0.254: J23.1 92.43,114.47 arc(92.73,113.74) 93.46,113.44 95.94,113.44 arc(96.44,113.23) 96.65,112.73 96.65,112.25 v2(96.62,112.23)
  BOTTOM w0.254: C142.2 96.65,110.13 96.65,112.2 v2(96.62,112.23)
DCLKOUT10N: length 2.4
  BOTTOM w0.254: U4.55 97.27,108.72 R87.1 97.39,108.83 C143.1
DCLKOUT10P: length 2.4
  BOTTOM w0.254: C142.1 96.62,108.83 R86.1 96.77,108.69 U4.54
DDBUS0: length 26.1
  TOP w0.279: U8.48 70.49,42.87 72.9,40.46 72.9,37.37 75.54,34.73 78.89,34.73 79.35,35.2 79.35,38.21 78.83,38.73 U11.3
DDBUS1: length 25
  TOP w0.279: U8.52 61.31,45.51 62.52,46.72 64.03,46.72 65.83,44.92 69.42,44.92 73.82,40.52 73.82,37.6 74.1,37.32 v1(74.82,37.32) ; v1(75.33,38.32) 75.56,38.08 U11.4
  BOTTOM w0.279: v1(74.82,37.32) 74.82,37.81 v1(75.33,38.32)
DDBUS2: length 32
  TOP w0.279: U8.53 60.81,45.95 v1(61.76,46.91) ; v1(78.77,37.43) U11.5
  BOTTOM w0.279: v1(61.76,46.91) 61.94,47.08 66.85,47.08 72.79,41.14 72.79,37.07 75.35,34.51 78.13,34.51 78.77,35.15 v1(78.77,37.43)
DDBUS3: length 26.6
  TOP w0.279: v1(60.88,46.85) 60.31,46.28 U8.54 ; U11.6 v1(76.11,36.78)
  BOTTOM w0.279: v1(60.88,46.85) 61.73,47.7 67.85,47.7 74.56,41 74.56,39.94 76.11,38.39 v1(76.11,36.78)
DDBUS4: length 39
  TOP w0.279: U12.3 83.46,48.47 84.57,47.36 84.57,43.48 81.75,40.66 74.67,40.66 67.74,47.59 60.89,47.59 59.81,46.5 U8.55
DDBUS5: length 38.2
  TOP w0.279: U12.4 83.09,47.82 83.87,47.04 83.87,43.73 81.57,41.43 75.06,41.43 68.1,48.4 60.43,48.4 58.8,46.77 U8.57
DDBUS6: length 32.3
  TOP w0.279: U12.5 v1(80.58,47.17) ; U8.58 v1(58.3,46.82)
  BOTTOM w0.279: v1(80.58,47.17) 80.25,46.84 80.25,45.52 77.48,42.74 74.56,42.74 68.98,48.32 59.81,48.32 v1(58.3,46.82)
DDBUS7: length 35.3
  TOP w0.279: U8.59 57.8,47.36 59.58,49.13 68.32,49.13 75.31,42.14 79.99,42.14 80.6,42.75 80.6,46.23 80.88,46.52 U12.6
DEVCLKIN: length 13.5
  TOP w0.279: T2.6 11.95,74.55 arc(11.12,74.38) 10.41,73.91 arc(9.71,73.44) 8.88,73.28 J18.1
DM: length 49.9
  TOP w0.152: R116.2 11.53,27.05 11.53,27.7 12.18,28.35 31.76,28.35 42.68,39.27 46.04,39.27 46.5,38.82 51.43,38.82 52.36,39.75 53.61,39.75 53.73,39.87 U8.7
DP: length 49.8
  TOP w0.152: R117.2 11.81,27.07 11.81,27.58 12.3,28.07 12.85,28.07 13.12,27.8 13.57,27.8 13.84,28.07 14.29,28.07 14.56,27.8 15.01,27.8 15.28,28.07 31.87,28.07 42.79,38.99 45.93,38.99 46.38,38.54 51.55,38.54 52.48,39.47 53.62,39.47 53.73,39.37 U8.8
EE_ADDR0_RX: length 20.8
  TOP w0.279: U5.1 124.6,43.9 127.75,47.05 130.8,47.05 131.37,46.48 v1(140.33,46.48)
EE_ADDR1_RX: length 22
  TOP w0.279: v1(139.06,45.21) 138.5,44.64 127.7,44.64 125.24,42.18 120.25,42.18 119.76,42.67 U5.2
EECLK: length 30.3
  TOP w0.279: U9.2 77.67,45.52 77.39,45.24 75.48,45.24 R124.2 75.38,44.79 75.08,44.49 74.13,44.49 68.71,49.92 58.4,49.92 56.3,47.82 U8.62
EECS: length 31.4
  TOP w0.279: U8.63 55.8,44.93 55.31,45.42 v1(53.75,45.42) ; v1(75.36,47.23) 75.38,47.22 R125.2 75.57,46.31 U9.1
  BOTTOM w0.279: v1(53.75,45.42) 53.75,47.2 56.3,49.75 72.84,49.75 v1(75.36,47.23)
EEDATA: length 30.1
  TOP w0.279: v1(77.5,44.05) 78.15,44.7 R131.1 78.32,44.8 U9.3 ; U8.61 v1(56.8,46.94)
  BOTTOM w0.279: v1(77.5,44.05) 74.4,44.05 69.45,48.99 57.84,48.99 56.8,47.95 v1(56.8,46.94)
FMC_SCL: length 40.1
  TOP w0.279: U5.6 118.49,39.91 116.47,41.93 116.47,45.35 118.11,46.99
  BOTTOM w0.102: 128.67,47.12 139.47,47.12 139.7,47.35 139.7,49.28 140.08,49.66 140.72,49.66 140.97,49.91 140.97,50.93 J25.C30
  BOTTOM w0.279: 128.67,47.12 127.38,47.12 125.98,45.72 119.38,45.72 118.11,46.99
FMC_SDA: length 37.2
  TOP w0.279: U5.5 117.22,39.79 115.57,41.44 J28.1
  BOTTOM w0.102: J25.C31 139.7,49.66 128.65,49.66
  BOTTOM w0.279: 128.65,49.66 118.24,49.66 J28.1
FPGA_JESD_CLK_A_N: length 59
  L04_SIG-1 w0.124: v1(139.06,83.31) 139.06,83.67 138.94,83.79 136.91,83.79 136.61,84.09 130.94,84.09 129.96,83.11 123.6,83.11 122.7,84.02 122.7,86.15 123.71,87.16 125.95,87.16 126.5,87.71 126.5,90.77 125.6,91.67 113.05,91.67 109.45,95.26 109.45,105.9 108.73,106.62 107.95,106.62 v2(107.72,106.4)
FPGA_JESD_CLK_A_P: length 59
  L04_SIG-1 w0.124: v1(139.06,84.58) 139.06,84.22 138.94,84.1 137.03,84.1 136.74,84.4 130.81,84.4 129.83,83.42 123.73,83.42 123,84.15 123,86.02 123.84,86.86 126.08,86.86 126.81,87.59 126.81,90.89 125.73,91.97 113.17,91.97 109.76,95.39 109.76,106.02 108.85,106.93 107.95,106.93 v2(107.72,107.16)
FPGA_JESD_CLK_B_N: length 59
  L04_SIG-1 w0.124: v1(135.25,80.77) 134.76,81.27 122.72,81.27 122.7,81.29 122.68,81.29 115.17,88.79 114.51,88.79 v1(114.23,88.51)
  BOTTOM w0.152: v1(114.23,88.51) 113.93,88.81 113.12,88.81 110.18,91.76 110.18,108.49 108.62,110.05 108.22,110.05 107.79,110.49 107.79,110.89 107.36,111.32 106.95,111.32 106.52,111.75 106.52,112.15 105.16,113.51 101.43,113.51 101.16,113.24 101.16,112.81 R127.2
FPGA_JESD_CLK_B_P: length 59
  L04_SIG-1 w0.124: v1(135.25,82.04) 134.79,81.57 122.84,81.57 115.3,89.12 114.5,89.12 v1(114.23,89.39)
  BOTTOM w0.152: v1(114.23,89.39) 113.92,89.09 113.24,89.09 110.46,91.87 110.46,108.61 105.28,113.79 101.32,113.79 100.88,113.36 100.88,112.81 R126.2
FPGA_JESD_CLK_C_N: length 97.1
  L04_SIG-1 w0.124: v1(92.88,111.21) 93.1,110.98 99.36,110.98 99.74,110.6 107.32,110.6 110.83,107.1 110.83,97.16 112.3,95.68 127.51,95.68 133.66,89.54 144.6,89.54 147.46,86.68 147.46,64.2 146.73,63.47 144.27,63.47 144.14,63.35 v2(144.14,62.99)
FPGA_JESD_CLK_C_P: length 97.1
  L04_SIG-1 w0.124: v2(144.14,64.26) 144.14,63.9 144.27,63.78 146.61,63.78 147.15,64.32 147.15,64.79 146.89,65.06 146.89,65.64 147.15,65.9 147.15,66.49 146.89,66.75 146.89,67.33 147.15,67.6 147.15,86.56 144.47,89.24 133.53,89.24 127.39,95.38 112.17,95.38 110.52,97.03 110.52,106.97 107.19,110.3 99.61,110.3 99.24,110.68 98.58,110.68 98.36,110.45 97.78,110.45 97.55,110.68 96.97,110.68 96.74,110.45 96.16,110.45 95.93,110.68 95.35,110.68 95.13,110.45 94.55,110.45 94.32,110.68 93.1,110.68 v1(92.88,110.45)
FPGA_JESD_SYSREFM: length 59
  L10_SIG-2 w0.14: v2(107.72,103.91) 107.95,104.13 108.49,104.13 109.58,103.04 109.58,93.73 104.75,88.89 104.75,83.58 110.05,78.28 113.85,78.28 115.92,80.36 128.19,80.36 131.1,77.44 135.12,77.44 135.25,77.3 v1(135.25,76.96)
FPGA_JESD_SYSREFP: length 59
  L10_SIG-2 w0.14: v2(107.72,104.67) 107.95,104.44 108.61,104.44 109.89,103.16 109.89,93.6 105.05,88.76 105.05,83.71 110.17,78.58 113.72,78.58 115.8,80.66 128.31,80.66 131.23,77.75 135.12,77.75 135.25,77.89 v1(135.25,78.23)
GTXCLKM: length 5
  BOTTOM w0.152: U4.2 103.12,105.81 103.23,105.92 104.5,105.92 105.22,106.64 105.88,106.64 106.07,106.45 R64.1 107.06,106.45 R129.1
GTXCLKP: length 5
  BOTTOM w0.152: R128.1 107.06,107.11 R65.1 106.07,107.11 105.88,106.92 105.1,106.92 104.39,106.2 103.23,106.2 103.12,106.31 U4.1
HSPC_PRSNT_M2C_L: length 23.1
  TOP w0.279: J30.1 126.21,93.6 127.21,92.6 141.05,92.6 144.14,89.51 v1(144.14,88.39)
INA+: length 1.5
  TOP w0.279: BALUN1.3 R1.1
INA-: length 1.5
  TOP w0.279: BALUN1.2 R4.1
INA_+: length 20.7
  TOP w0.279: R180.1 27.58,81.3 arc(27.09,80.12) 25.91,79.63 J1.1
INA_-: length 20.7
  TOP w0.279: R179.1 27.58,88.12 27.58,90.63 arc(27.08,91.83) 25.88,92.33 J3.1
INAN: length 14.9
  TOP w0.279: R4.2 31.32,87.5 arc(31.83,87.4) 32.27,87.11 33.5,85.88 arc(33.77,85.48) 33.86,85.02 33.86,78 arc(33.82,77.83) U1.A5
INAP: length 14.9
  TOP w0.279: R180.2 28.45,84.45 arc(28.63,84.53) 28.7,84.71 28.7,84.96 arc(28.78,85.15) 28.97,85.23 29.63,85.23 arc(29.87,85.13) 29.97,84.89 29.97,84.25 arc(30.01,84.09) 30.1,83.95 30.14,83.91 arc(30.23,83.84) 30.34,83.82 30.96,83.82 arc(31.16,83.91) 31.24,84.1 31.24,84.59 arc(31.26,84.7) 31.32,84.79 31.46,84.92 arc(31.58,85.01) 31.74,85.04 32.25,85.04 arc(32.42,85) 32.57,84.91 32.63,84.84 arc(32.75,84.67) 32.79,84.46 32.79,78 arc(32.83,77.83) U1.A4
INB+: length 1.5
  TOP w0.279: 25.43,62.1 R6.1
INB-: length 1.5
  TOP w0.279: BALUN2.3 R9.1
INB_+: length 20.7
  TOP w0.279: R151.1 27.58,62.72 27.58,65.23 arc(27.08,66.43) 25.88,66.93 J4.1
INB_-: length 20.7
  TOP w0.279: J6.1 25.91,54.23 arc(27.09,54.72) 27.58,55.9 R162.1
INBN: length 14.9
  TOP w0.279: R9.2 31.32,59.05 arc(31.83,59.16) 32.27,59.45 33.5,60.68 arc(33.77,61.07) 33.86,61.54 33.86,68.56 arc(33.82,68.73) U1.M5
INBP: length 14.9
  TOP w0.279: R6.2 28.45,62.1 arc(28.63,62.03) 28.7,61.85 28.7,61.59 arc(28.79,61.39) 28.99,61.31 29.61,61.31 arc(29.87,61.41) 29.97,61.67 29.97,62.3 arc(30.01,62.47) 30.1,62.61 30.14,62.65 arc(30.23,62.71) 30.34,62.73 30.96,62.73 arc(31.16,62.65) 31.24,62.46 31.24,61.96 arc(31.26,61.86) 31.32,61.77 31.44,61.65 arc(31.59,61.55) 31.75,61.52 32.25,61.52 arc(32.42,61.55) 32.57,61.65 32.63,61.72 arc(32.75,61.89) 32.79,62.1 32.79,68.56 arc(32.83,68.73) U1.M4
JESD_SYSREFM: length 5
  BOTTOM w0.152: R60.1 107.06,103.96 R61.1 106.07,103.96 105.88,104.15 105.37,104.15 104.6,104.92 103.23,104.92 103.12,104.81 U4.4
JESD_SYSREFP: length 5
  BOTTOM w0.152: U4.3 103.13,105.31 103.24,105.2 104.71,105.2 105.49,104.43 105.88,104.43 106.07,104.62 R62.1 107.06,104.62 R59.1
LM95233_SMBCLK: length 142
  TOP w0.279: U2.13 30.64,111.2 v1(31.93,112.49)
  L10_SIG-2 w0.165: v1(59.82,30.61) 41.99,30.61 33.79,38.81 33.79,43.57 34.73,44.51 44.2,44.51 49.78,50.1 49.78,96.14 48.62,97.31 48.62,116.91 47.85,117.68 40.35,117.68 34.64,111.98 32.44,111.98 v1(31.93,112.49)
LM95233_SMBDAT: length 137.8
  TOP w0.279: U2.12 31.28,110.7 v1(31.93,111.34) ; v1(65.79,28.57) 62.1,28.57 60.96,29.72 R113.2
  L10_SIG-2 w0.165: v1(31.93,111.34) 31.55,111.34 31.29,111.6 31.29,112.87 31.55,113.12 33.85,113.12 41.11,120.39 47.41,120.39 49.61,118.18 50.01,118.18 51.23,116.97 51.23,113.53 53.05,111.71 53.05,100.75 52.04,99.74 52.04,97.17 51.51,96.64 51.51,56.67 57.64,50.55 65.41,50.55 68.23,47.73 68.23,31.57 65.79,29.12 v1(65.79,28.57)
  BOTTOM w0.279: R110.2 66.04,28.83 v1(65.79,28.57)
LMK04828_CSB: length 108.1
  TOP w0.279: TP36.1 72.39,32.89 70.99,34.29 R120.2
  L10_SIG-2 w0.165: v1(101.27,94.61) 101.27,56.44 103.79,53.92 103.79,33.64 99.62,29.47 73.27,29.47 TP36.1
  BOTTOM w0.279: U4.18 v1(101.27,94.61)
LMK04828_SYNC: length 4.1
  TOP w0.279: v1(132.72,70.61) 132.08,71.25 R97.2
LMK LOCKED:
  vias: v1(50.08,121.99)
LMK_CLKIN: length 6.1
  BOTTOM w0.279: J22.1 R71.1 R70.1
LMK_LMX_CLK: length 146.3
  TOP w0.279: R118.2 v1(68.96,35.73) ; v1(61.93,112.47) 61.93,109.85 62.41,109.37 68.55,109.37 75.06,102.86 75.06,98.74 80.54,93.25 v1(100.73,93.25)
  L10_SIG-2 w0.165: v1(61.93,112.47) 61.81,112.36 59.11,112.36 55.21,108.46 55.21,97.16 56.04,96.33 56.04,66.26 70.87,51.44 70.87,37.63 v1(68.96,35.73)
  BOTTOM w0.279: v1(61.93,112.47) 61.93,112.64 61.86,112.71 61.86,113.18 61.8,113.23 U3.16 ; U4.19 100.77,93.29 v1(100.73,93.25)
